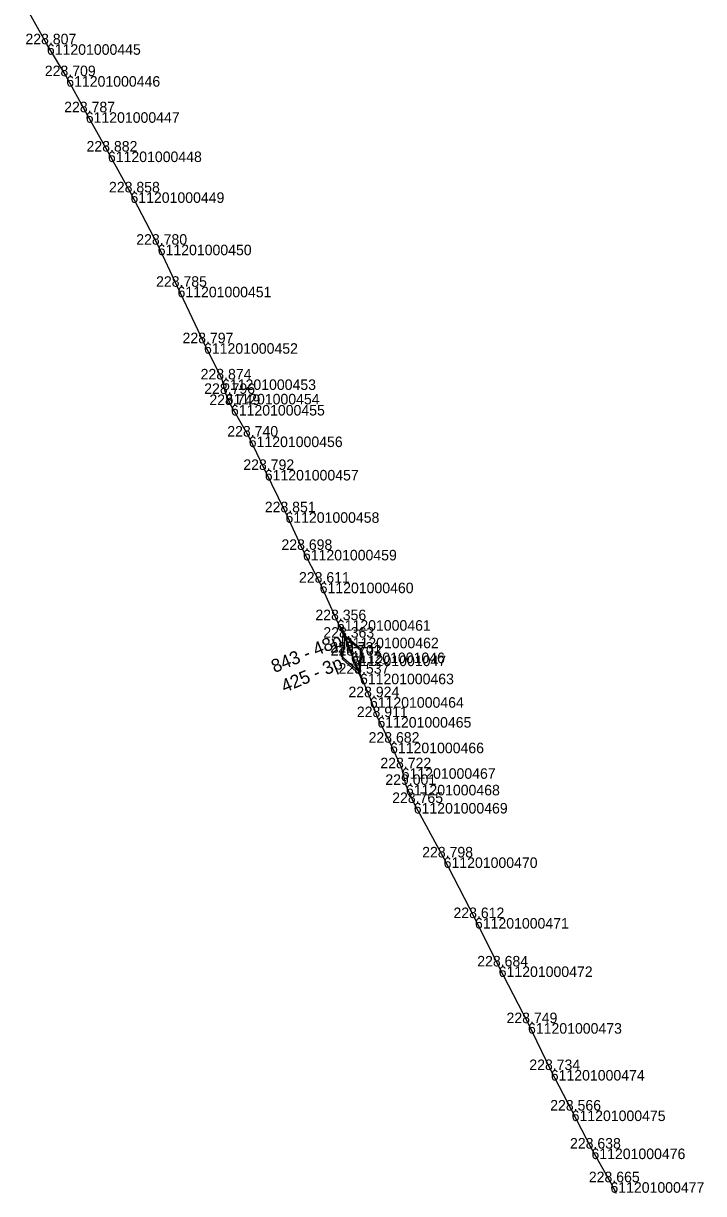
# Model space of a CAD drawing. Extents: x -771040 to -768909, y -1052366 to -1050115.
# Drawn here: x -769527.3 to -769449.8, y -1050518.1 to -1050384.6 of the extents above; entities that cross this region are included whole.
import ezdxf

# ---------------------------------------------------------------- set-up
doc = ezdxf.new("R2010")
doc.units = 0
for name, color, linetype in [('Vrstva 28', 7, 'Continuous'), ('Vrstva 60', 7, 'Continuous'), ('Vrstva 61', 7, 'Continuous')]:
    doc.layers.add(name, color=color, linetype=linetype)

msp = doc.modelspace()

# ---------------------------------------------------------------- linework, layer by layer
at = {"layer": 'Vrstva 28'}
for p, q in [((-769491.34, -1050453.12), (-769488.61, -1050459.55)), ((-769491.08, -1050453.41), (-769488.6, -1050459.94)), ((-769491.05, -1050456.79), (-769490.89, -1050454.19)), ((-769490.89, -1050454.19), (-769488.91, -1050455.88)), ((-769490.93, -1050457.09), (-769490.66, -1050454.5)), ((-769490.66, -1050454.5), (-769488.75, -1050456.26)), ((-769489.07, -1050458.48), (-769491.05, -1050456.79)), ((-769488.91, -1050455.88), (-769489.07, -1050458.48)), ((-769488.75, -1050456.26), (-769489.01, -1050458.85)), ((-769489.01, -1050458.85), (-769490.93, -1050457.09))]:
    msp.add_line(p, q, dxfattribs=at)
msp.add_lwpolyline([(-769459.69, -1050518.07), (-769460.39, -1050516.77), (-769462.55, -1050512.93), (-769464.81, -1050508.59), (-769467.19, -1050503.97), (-769469.79, -1050498.62), (-769473.13, -1050492.15), (-769475.84, -1050486.63), (-769479.41, -1050479.71), (-769482.82, -1050473.5), (-769483.71, -1050471.43), (-769484.19, -1050469.54), (-769485.52, -1050466.62), (-769486.96, -1050463.7), (-769487.82, -1050461.43), (-769488.95, -1050458.75), (-769489.84, -1050456.68), (-769489.98, -1050456.34), (-769490.68, -1050454.64), (-769491.59, -1050452.64), (-769493.55, -1050448.36), (-769495.46, -1050444.62), (-769497.45, -1050440.33), (-769499.81, -1050435.5), (-769501.64, -1050431.69), (-769503.67, -1050428.09), (-769504.27, -1050426.82), (-769504.68, -1050425.17), (-769506.74, -1050421.04), (-769509.76, -1050414.6), (-769512.02, -1050409.8), (-769515.13, -1050403.83), (-769517.7, -1050399.17), (-769520.23, -1050394.69), (-769522.45, -1050390.57), (-769524.66, -1050386.93), (-769527.34, -1050382.17)], dxfattribs=at)
at = {"layer": 'Vrstva 60'}
for p, q in [((-769524.66, -1050386.93), (-769524.66, -1050386.93)), ((-769522.45, -1050390.57), (-769522.45, -1050390.57)), ((-769520.23, -1050394.69), (-769520.23, -1050394.69)), ((-769517.7, -1050399.17), (-769517.7, -1050399.17)), ((-769515.13, -1050403.83), (-769515.13, -1050403.83)), ((-769512.02, -1050409.8), (-769512.02, -1050409.8)), ((-769509.76, -1050414.6), (-769509.76, -1050414.6)), ((-769506.74, -1050421.04), (-769506.74, -1050421.04)), ((-769504.68, -1050425.17), (-769504.68, -1050425.17)), ((-769504.27, -1050426.82), (-769504.27, -1050426.82)), ((-769503.67, -1050428.09), (-769503.67, -1050428.09)), ((-769501.64, -1050431.69), (-769501.64, -1050431.69)), ((-769499.81, -1050435.5), (-769499.81, -1050435.5)), ((-769497.45, -1050440.33), (-769497.45, -1050440.33)), ((-769495.46, -1050444.62), (-769495.46, -1050444.62)), ((-769493.55, -1050448.36), (-769493.55, -1050448.36)), ((-769491.59, -1050452.64), (-769491.59, -1050452.64)), ((-769490.68, -1050454.64), (-769490.68, -1050454.64)), ((-769489.98, -1050456.34), (-769489.98, -1050456.34)), ((-769489.84, -1050456.68), (-769489.84, -1050456.68)), ((-769488.95, -1050458.75), (-769488.95, -1050458.75)), ((-769487.82, -1050461.43), (-769487.82, -1050461.43)), ((-769486.96, -1050463.7), (-769486.96, -1050463.7)), ((-769485.52, -1050466.62), (-769485.52, -1050466.62)), ((-769484.19, -1050469.54), (-769484.19, -1050469.54)), ((-769483.71, -1050471.43), (-769483.71, -1050471.43)), ((-769482.82, -1050473.5), (-769482.82, -1050473.5)), ((-769479.41, -1050479.71), (-769479.41, -1050479.71)), ((-769475.84, -1050486.63), (-769475.84, -1050486.63)), ((-769473.13, -1050492.15), (-769473.13, -1050492.15)), ((-769469.79, -1050498.62), (-769469.79, -1050498.62)), ((-769467.19, -1050503.97), (-769467.19, -1050503.97)), ((-769464.81, -1050508.59), (-769464.81, -1050508.59)), ((-769462.55, -1050512.93), (-769462.55, -1050512.93)), ((-769460.39, -1050516.77), (-769460.39, -1050516.77))]:
    msp.add_line(p, q, dxfattribs=at)

# ---------------------------------------------------------------- texts
at = {"layer": 'Vrstva 28'}
for s, rotation, p in [('843 - 48p', 22.2077, (-769498.7, -1050458.68)), ('425 - 3p', 23.0156, (-769497.55, -1050460.94))]:
    msp.add_text(s, height=1.5, rotation=rotation, dxfattribs=at).set_placement(p)
at = {"layer": 'Vrstva 60'}
for s, p in [('611201000445', (-769524.66, -1050388.13)), ('611201000446', (-769522.45, -1050391.77)), ('611201000447', (-769520.23, -1050395.89)), ('611201000448', (-769517.7, -1050400.37)), ('611201000449', (-769515.13, -1050405.03)), ('611201000450', (-769512.02, -1050411)), ('611201000451', (-769509.76, -1050415.8)), ('611201000452', (-769506.74, -1050422.24)), ('611201000453', (-769504.68, -1050426.37)), ('611201000454', (-769504.27, -1050428.02)), ('611201000455', (-769503.67, -1050429.29)), ('611201000456', (-769501.64, -1050432.89)), ('611201000457', (-769499.81, -1050436.7)), ('611201000458', (-769497.45, -1050441.53)), ('611201000459', (-769495.46, -1050445.82)), ('611201000460', (-769493.55, -1050449.56)), ('611201000461', (-769491.59, -1050453.84)), ('611201000462', (-769490.68, -1050455.84)), ('611201001046', (-769489.98, -1050457.54)), ('611201001047', (-769489.84, -1050457.88)), ('611201000463', (-769488.95, -1050459.95)), ('611201000464', (-769487.82, -1050462.63)), ('611201000465', (-769486.96, -1050464.9)), ('611201000466', (-769485.52, -1050467.82)), ('611201000467', (-769484.19, -1050470.74)), ('611201000468', (-769483.71, -1050472.63)), ('611201000469', (-769482.82, -1050474.7)), ('611201000470', (-769479.41, -1050480.91)), ('611201000471', (-769475.84, -1050487.83)), ('611201000472', (-769473.13, -1050493.35)), ('611201000473', (-769469.79, -1050499.82)), ('611201000474', (-769467.19, -1050505.17)), ('611201000475', (-769464.81, -1050509.79)), ('611201000476', (-769462.55, -1050514.13)), ('611201000477', (-769460.39, -1050517.97))]:
    msp.add_text(s, height=1.2, dxfattribs=at).set_placement(p)
at = {"layer": 'Vrstva 61'}
for s, p in [('228.807', (-769527.11, -1050386.93)), ('228.709', (-769524.9, -1050390.57)), ('228.787', (-769522.69, -1050394.69)), ('228.882', (-769520.14, -1050399.17)), ('228.858', (-769517.58, -1050403.83)), ('228.780', (-769514.47, -1050409.8)), ('228.785', (-769512.21, -1050414.6)), ('228.797', (-769509.19, -1050421.04)), ('228.874', (-769507.13, -1050425.17)), ('228.796', (-769506.72, -1050426.82)), ('228.749', (-769506.13, -1050428.09)), ('228.740', (-769504.09, -1050431.69)), ('228.792', (-769502.26, -1050435.5)), ('228.851', (-769499.81, -1050440.33)), ('228.698', (-769497.91, -1050444.62)), ('228.611', (-769495.91, -1050448.36)), ('228.356', (-769494.04, -1050452.64)), ('228.363', (-769493.13, -1050454.64)), ('228.731', (-769492.34, -1050456.34)), ('228.702', (-769492.29, -1050456.68)), ('228.537', (-769491.4, -1050458.75)), ('228.924', (-769490.27, -1050461.43)), ('228.911', (-769489.31, -1050463.7)), ('228.682', (-769487.97, -1050466.62)), ('228.722', (-769486.63, -1050469.54)), ('229.001', (-769486.06, -1050471.43)), ('228.765', (-769485.28, -1050473.5)), ('228.798', (-769481.86, -1050479.71)), ('228.612', (-769478.29, -1050486.63)), ('228.684', (-769475.58, -1050492.15)), ('228.749', (-769472.24, -1050498.62)), ('228.734', (-769469.64, -1050503.97)), ('228.566', (-769467.26, -1050508.59)), ('228.638', (-769465, -1050512.93)), ('228.665', (-769462.85, -1050516.77))]:
    msp.add_text(s, height=1.2, dxfattribs=at).set_placement(p)

doc.saveas('drawing.dxf')
